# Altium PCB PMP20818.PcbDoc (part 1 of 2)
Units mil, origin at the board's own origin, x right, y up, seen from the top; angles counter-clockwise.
Board outline 3200 x 3200 mil, 4 copper layers (Top Layer, Signal Layer 1, Signal Layer 2, Bottom Layer), stack 61.2 mil thick; 130 components, 48 nets, 295 pads, 106 vias.
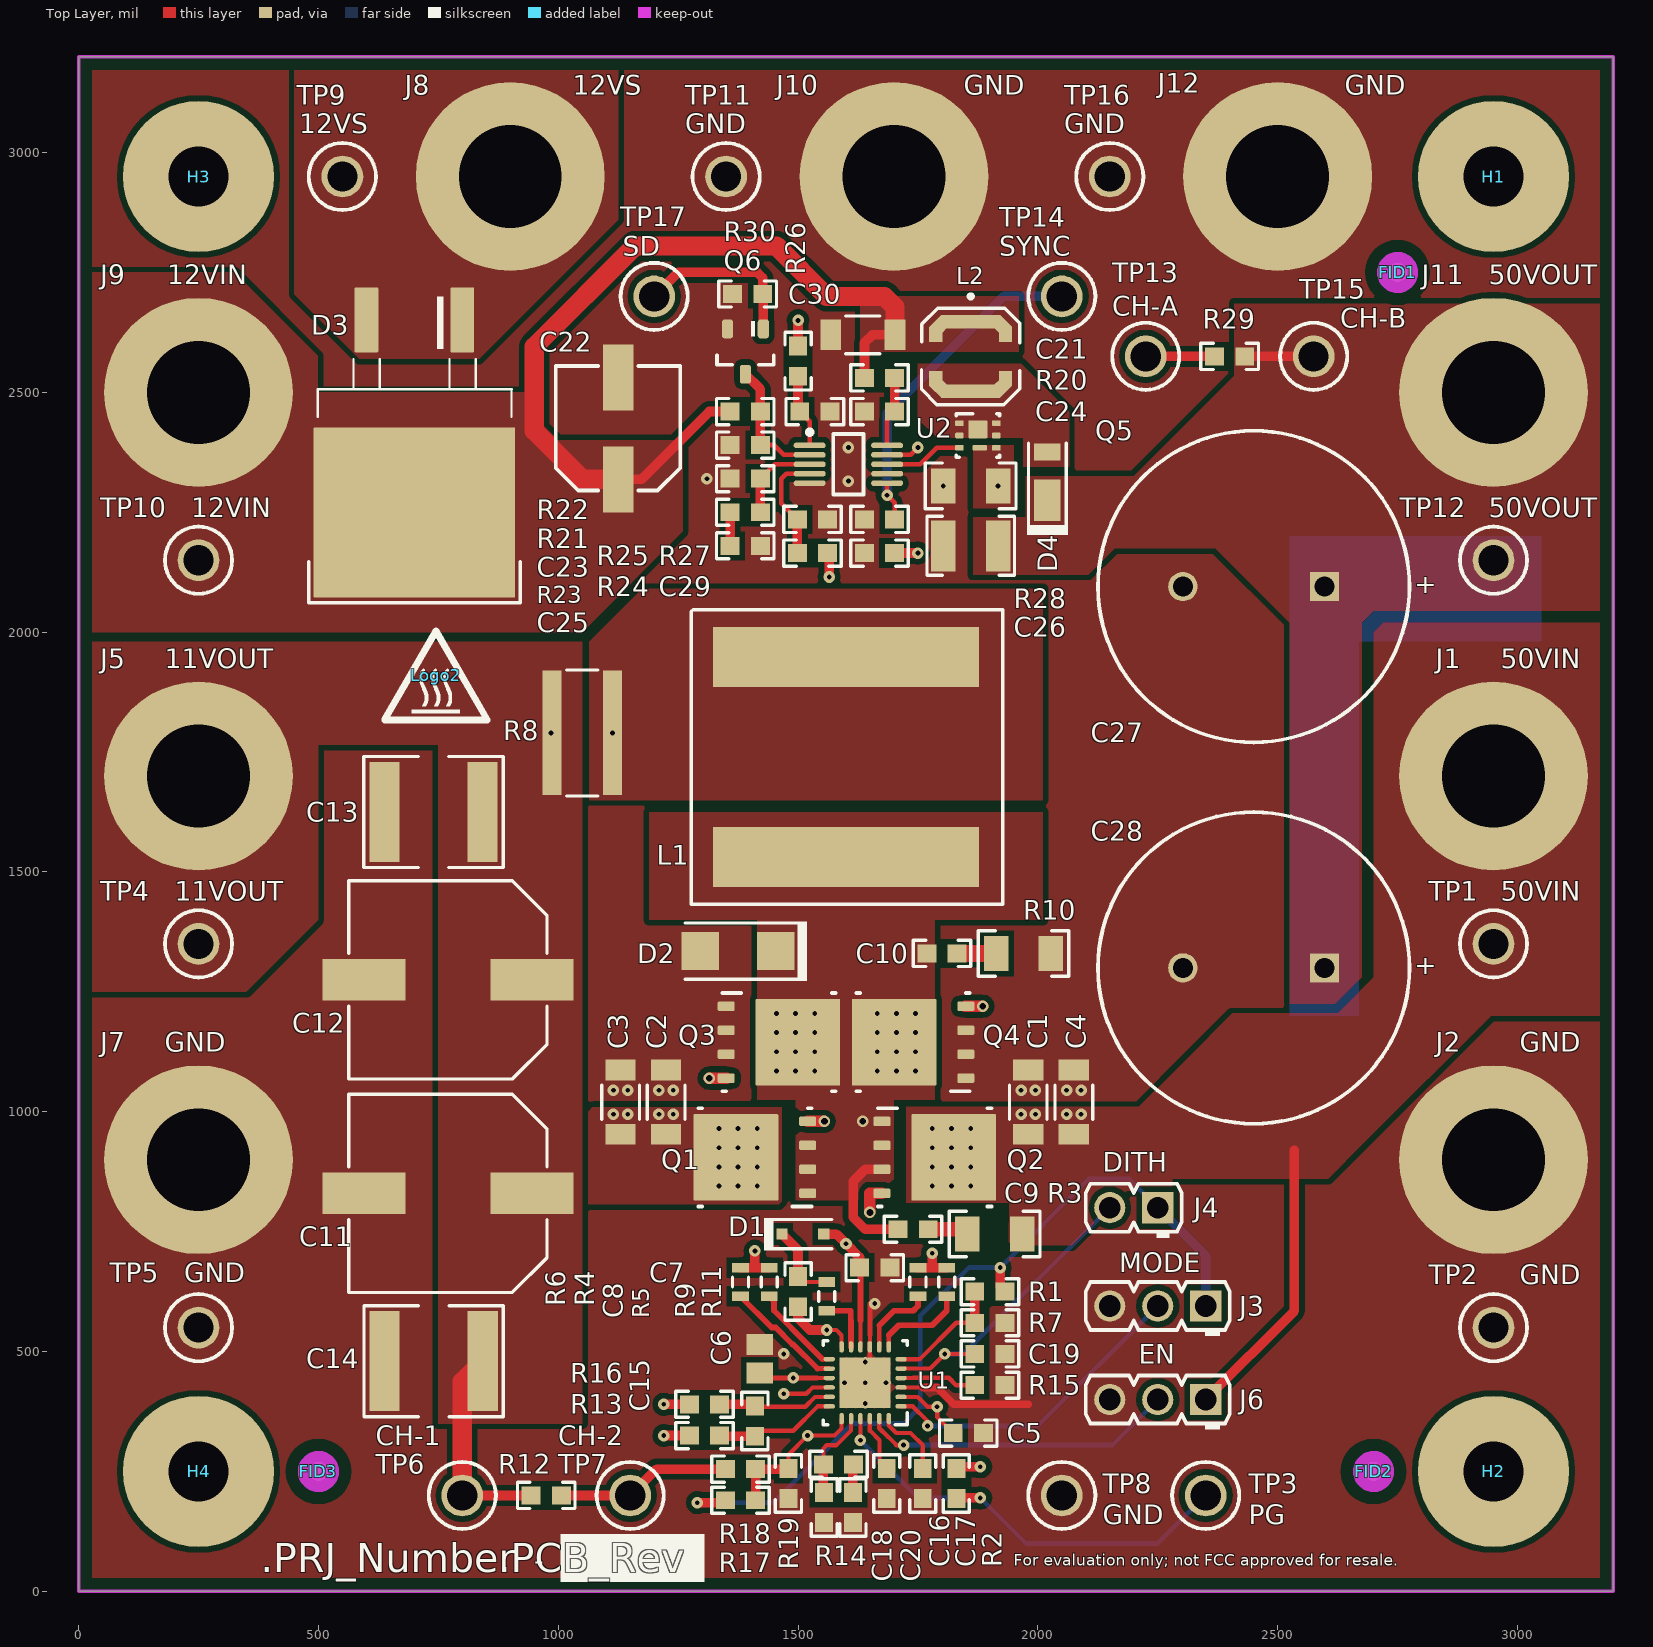
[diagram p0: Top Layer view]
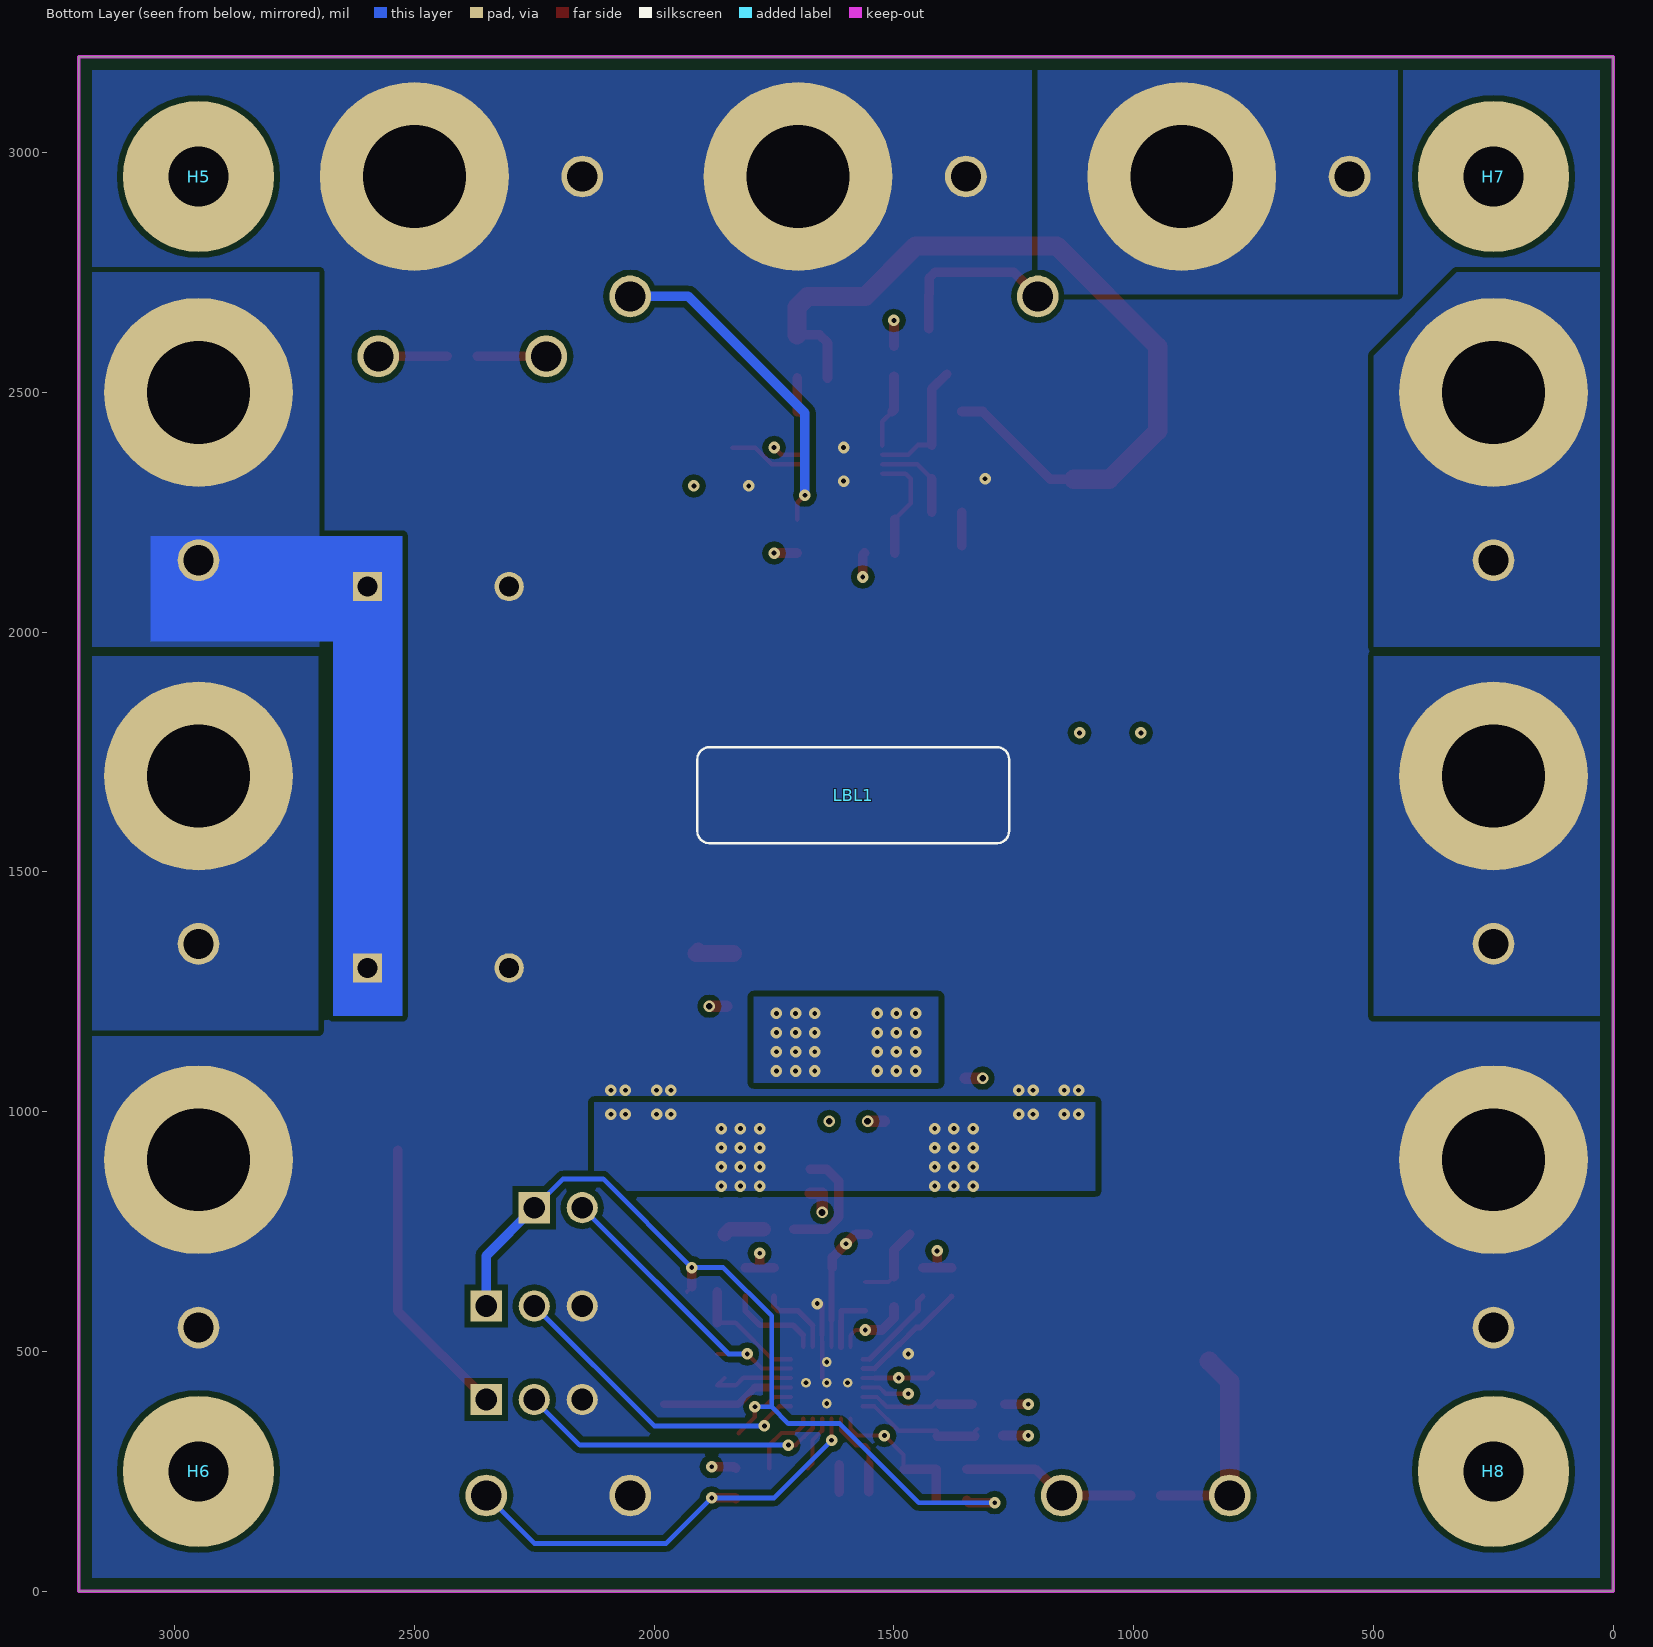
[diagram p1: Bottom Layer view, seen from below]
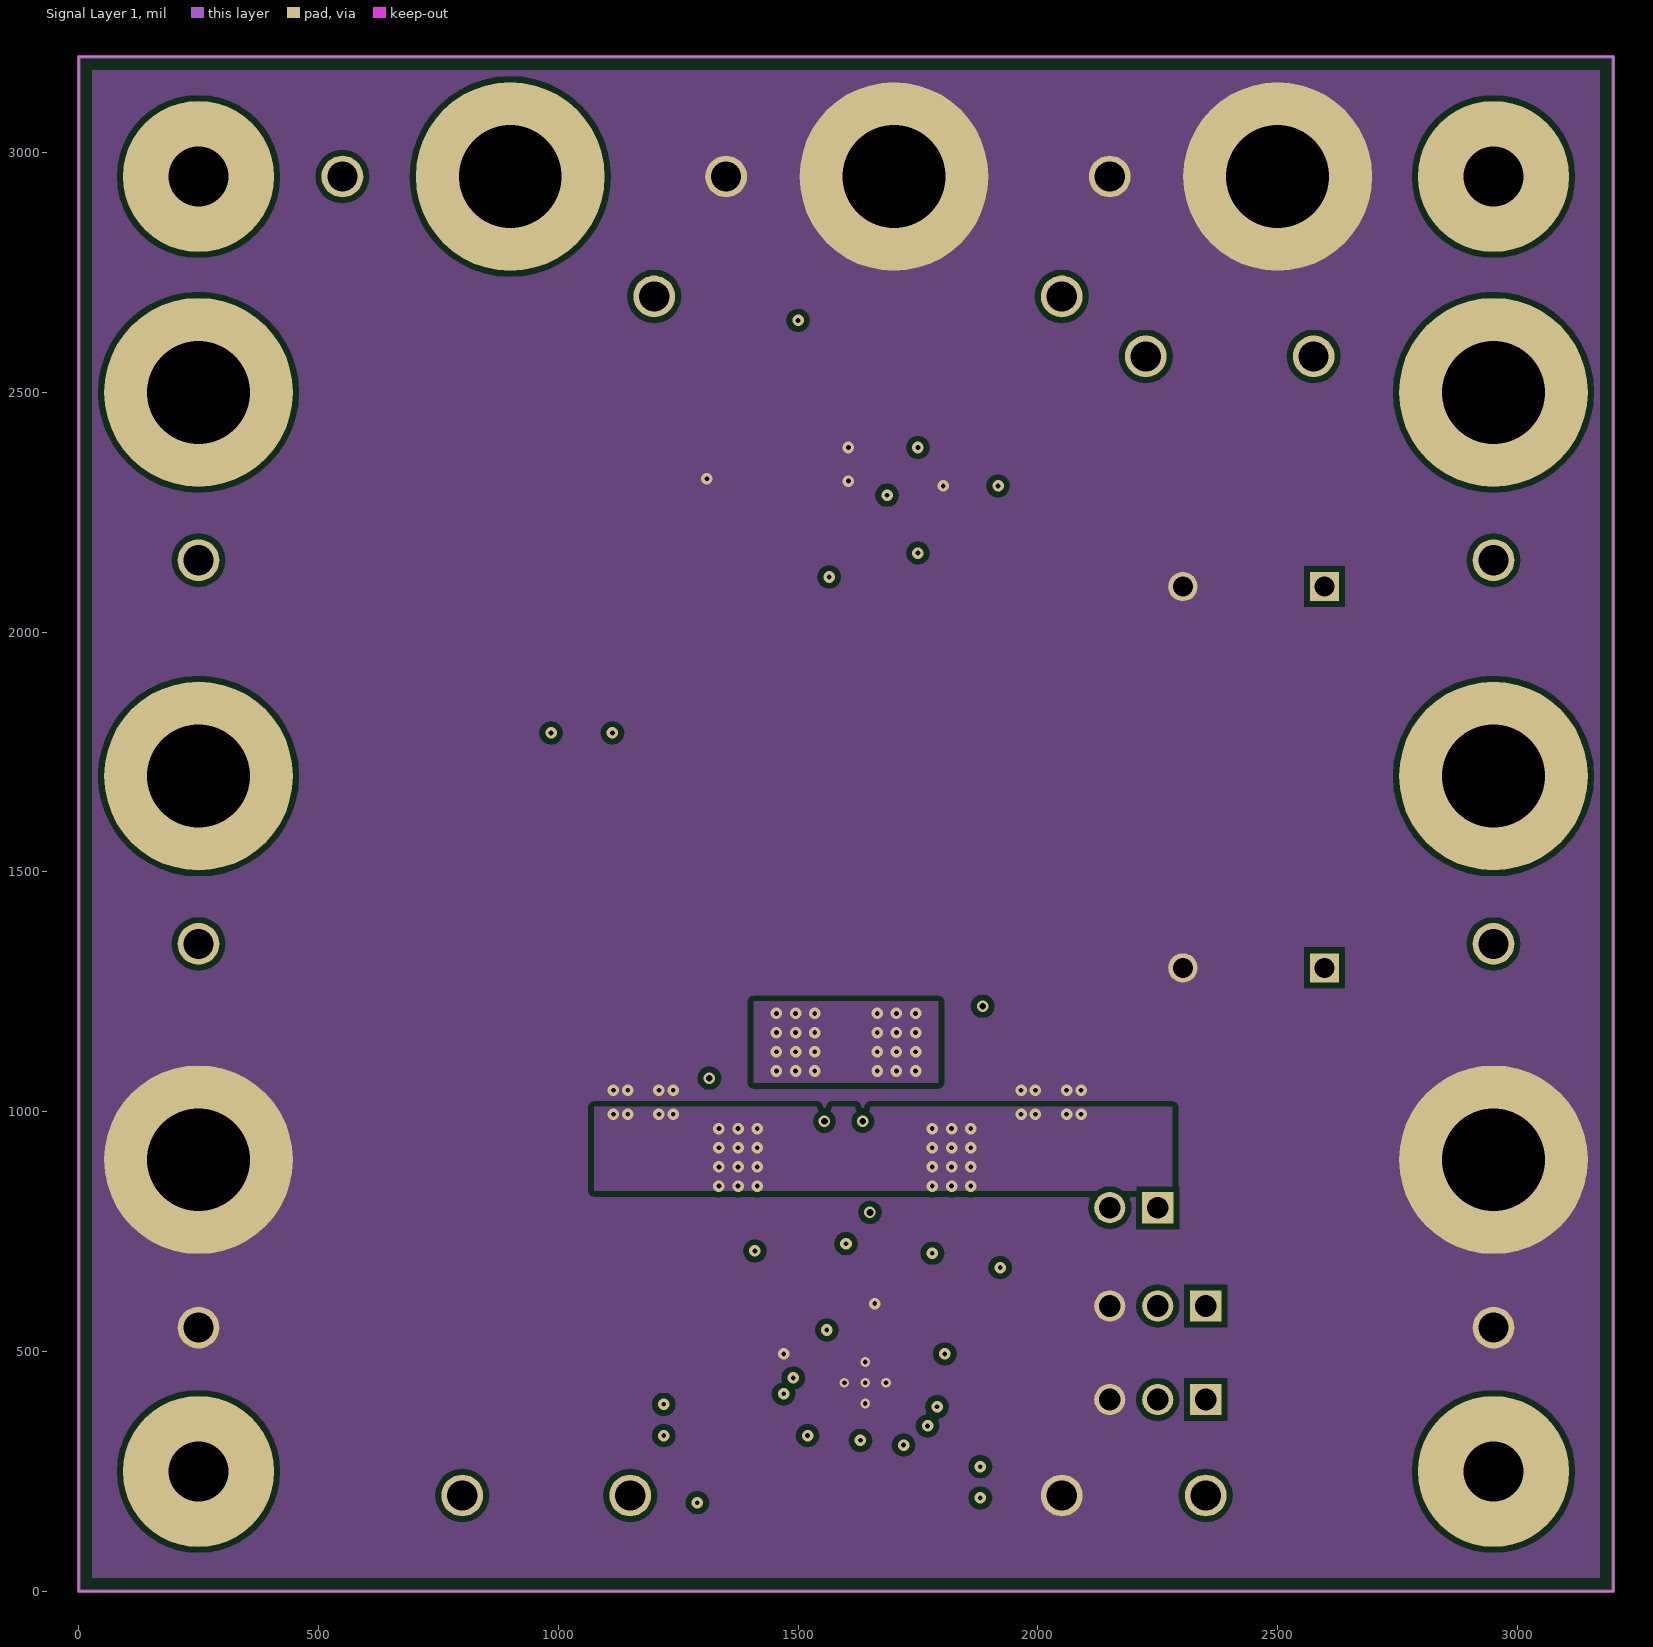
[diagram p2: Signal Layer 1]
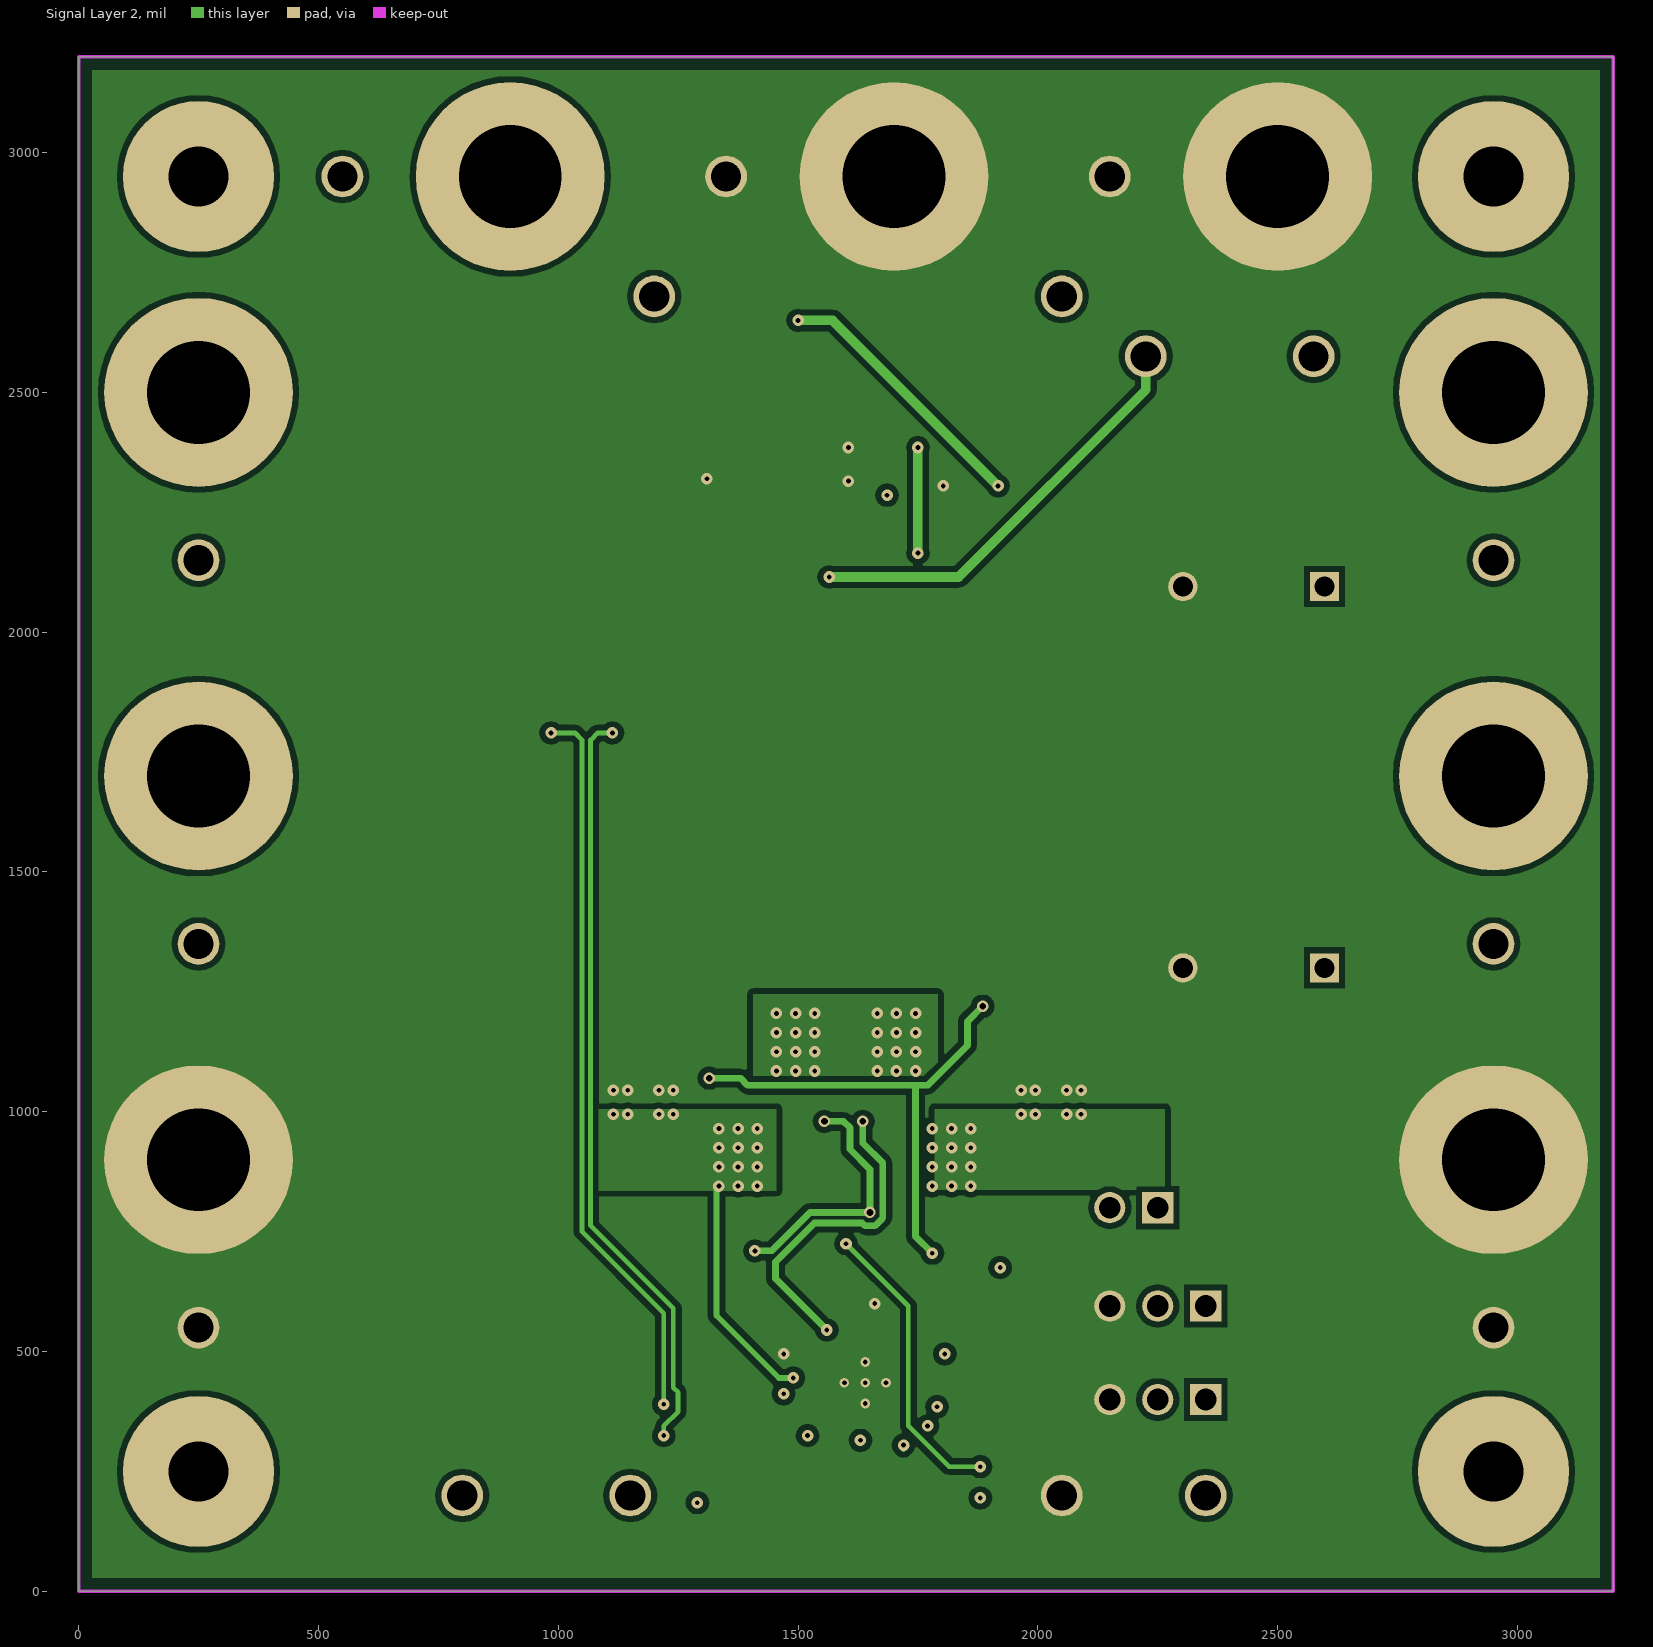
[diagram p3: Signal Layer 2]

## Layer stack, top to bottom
Top Solder: solder mask 0.4, Solder Resist, Dk 3.5
Top Layer: signal copper 2.8
Dielectric1: core 16, FR-4, Dk 4.8
Signal Layer 1: signal copper 2.8
Dielectric 3: prepreg 18, Dk 4.2
Signal Layer 2: signal copper 2.8
Dielectric 2: core 16, FR-4, Dk 4.2
Bottom Layer: signal copper 2.8
Bottom Solder: solder mask 0.4, Solder Resist, Dk 3.5

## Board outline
0,0 3200,0 3200,3200 0,3200

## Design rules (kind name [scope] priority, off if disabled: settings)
AcuteAngle [All] p1: minimum=4.50000000000000E+0001 checktracksonly=FALSE
AssemblyTestPointUsage [All] p1: valid=2
Clearance ClearanceNetTie [HasFootprint('RGE0024H') vs HasFootprint('Net-Tie_10mil')] p1: gap=0
Clearance Clearance_Keepouts [((IsTrack Or IsArc) And Not InPoly) And IsFree and IsKeepOut vs ((IsTrack Or IsArc) And Not InPoly) And IsFree and IsKeepOut] p2: gap=0
Clearance Clearance_BoardEdge_MountingHoles [OnCopper and InComponentClass('Mounting Holes') vs IsKeepOut] p3: gap=40
Clearance Clearance_BoardEdge_Poly [OnCopper and InPoly vs IsKeepOut] p4: gap=25
Clearance Clearance_BoardEdge [OnCopper and Not InComponentClass('Logo') and not InComponentClass('FiducialMark') and not InRegion(1000,500,4000,800) and Not IsKeepout vs IsKeepOut] p5: gap=40
Clearance Clearance_Poly [InPolygon] p6: gap=12
Clearance [All] p7: gap=7.87
ComponentClearance ComponentClearance_L2_L5 [HasFootprint('IHLP2525CZ') vs HasFootprint('IHLP-4040DZ')] p1: gap=0 collisioncheckmode=3 verticalgap=0 showdistances=FALSE
ComponentClearance ComponentClearanceNetTie [HasFootprint('RGE0024H') vs HasFootprint('Net-Tie_10mil')] p2: gap=0 collisioncheckmode=3 verticalgap=0 showdistances=FALSE
ComponentClearance ComponentClearance_MountingHoles_FiducialMarks [InComponentClass('Mounting Holes') vs InComponentClass('FiducialMark')] p3: gap=50 collisioncheckmode=3 verticalgap=10 showdistances=FALSE
ComponentClearance ComponentClearance_Shunt [InComponentClass('Header') vs InComponentClass('Shunt')] p4: gap=0 collisioncheckmode=3 verticalgap=0 showdistances=FALSE
ComponentClearance ComponentClearance_Logo [InComponentClass('Logo')] p5: gap=50 collisioncheckmode=3 verticalgap=10 showdistances=FALSE
ComponentClearance ComponentClearance_ScrewToNut [(HasFootprint('NY PMS 440 0025 PH')) vs (HasFootprint('Keystone_1902C'))] p6: gap=5 collisioncheckmode=3 verticalgap=10 showdistances=FALSE
ComponentClearance ComponentClearance_MountingHoles [InComponentClass('Mounting Holes')] p7: gap=100 collisioncheckmode=3 verticalgap=200 showdistances=FALSE
ComponentClearance ComponentClearance_SmallPassives [HasFootprint('0201*') or HasFootprint('0402*') or HasFootprint('0508') or HasFootprint('0603*') or HasFootprint('0612') or HasFootprint('0805*') or HasFootprint('0815*') or HasFootprint('0830*') or HasFootprint('1206*') or HasFootprint('1210*') or HasFootprint('1808*') or HasFootprint('1812*') or HasFootprint('1825*') or HasFootprint('2010*') or HasFootprint('2220*') or HasFootprint('2225*') or HasFootprint('2512*') or HasFootprint('2728*') or HasFootprint('3518*') vs HasFootprint('0201*') or HasFootprint('0402*') or HasFootprint('0508') or HasFootprint('0603*') or HasFootprint('0612') or HasFootprint('0805*') or HasFootprint('0815*') or HasFootprint('0830*') or HasFootprint('1206*') or HasFootprint('1210*') or HasFootprint('1808*') or HasFootprint('1812*') or HasFootprint('1825*') or HasFootprint('2010*') or HasFootprint('2220*') or HasFootprint('2225*') or HasFootprint('2512*') or HasFootprint('2728*') or HasFootprint('3518*')] p8: gap=20 collisioncheckmode=3 verticalgap=10 showdistances=FALSE
ComponentClearance ComponentClearance_THtoSMT [IsThruComponent vs IsSMTComponent] p9: gap=25 collisioncheckmode=3 verticalgap=30 showdistances=FALSE
ComponentClearance ComponentClearance_THtoTH [IsThruComponent vs IsThruComponent] p10: gap=25 collisioncheckmode=3 verticalgap=30 showdistances=FALSE
ComponentClearance [All] p11: gap=20 collisioncheckmode=3 verticalgap=10 showdistances=FALSE
DiffPairsRouting [All] p1: maxlimit=100 minlimit=10 mostfreqgap=10 toplayer_minwidth=15 toplayer_maxwidth=15 toplayer_prefwidth=15 midlayer1_minwidth=15 midlayer1_maxwidth=15 midlayer1_prefwidth=15 midlayer2_minwidth=15 midlayer2_maxwidth=15 midlayer2_prefwidth=15 bottomlayer_minwidth=15 bottomlayer_maxwidth=15 bottomlayer_prefwidth=15 maxuncoupledlength=1000
FabricationTestPointUsage TestPointUsage [All] p1: valid=2 allowmultiple=FALSE
FabricationTestpoint Testpoint [All] p1: side=3 testpointundercomponent=TRUE minsize=40 maxsize=100 preferedsize=60 minholesize=0 maxholesize=40 preferedholesize=32 testpointgrid=1 allowsidetop=TRUE allowsidebottom=TRUE usegrid=TRUE gridtolerance=0.01
FanoutControl Fanout_LCC [IsLCC] p1: bgadir=Out bgaviamode=Centered fanoutstyle=Auto fanoutdirection=Alternating viagrid=1 // Fanout_LCC (Default Rule)
FanoutControl Fanout_BGA [IsBGA] p2: bgadir=Out bgaviamode=Centered fanoutstyle=Auto fanoutdirection=Alternating viagrid=1 // Fanout_BGA (Default Rule)
FanoutControl Fanout_Default [All] p4: bgadir=Out bgaviamode=Centered fanoutstyle=Auto fanoutdirection=Alternating viagrid=1 // Fanout_Default (Default Rule)
FanoutControl Fanout_Small [(CompPinCount < 5)] p5: bgadir=Out bgaviamode=Centered fanoutstyle=Auto fanoutdirection=OutThenIn viagrid=1 // Fanout_Small (Default Rule)
Height [All] p1: minheight=0 maxheight=1500 prefheight=500
HoleSize [All] p1: absolutevalues=TRUE maxlimit=251 minlimit=8 maxpercent=80.000 minpercent=20.000
MinimumAnnularRing MinimumAnnularRing_ThermalPadVias [IsVia and InAnyComponent] p1: minimumring=5
MinimumAnnularRing [All] p2: minimumring=5
MinimumSolderMaskSliver MinimumSolderMaskSliver_Logo [InComponentClass('Logo') vs InComponentClass('Logo')] p1: minsoldermaskwidth=0.7
MinimumSolderMaskSliver [All] p2: minsoldermaskwidth=3.94
PlaneConnect [All] p1: planeconnectstyle=Direct reliefexpansion=10 reliefentries=4 reliefconductorwidth=10 reliefairgap=10
PolygonConnect [All] p1: connectstyle=Direct reliefconductorwidth=10 reliefentries=4 polygonreliefangle="90 Angle" airgapwidth=10
RoutingVias ThermalPadVias [IsVia and InAnyComponent] p1: holewidth=8 width=18 viastyle="Through Hole" minholewidth=8 minwidth=18 maxholewidth=20 maxwidth=30
RoutingVias [All] p2: holewidth=16 width=34 viastyle="Through Hole" minholewidth=8 minwidth=18 maxholewidth=40 maxwidth=65
SilkToBoardRegionClearance [Not ((IsComment or IsDesignator) And (Hide <> 'False')) and not InRegion(1000,500,4000,800)] p1:
SilkToSilkClearance SilkToSilkClearance_Pb-FreeLogo [(HasFootprint('Pb-Free_Overlay_Medium') OR HasFootprint('Pb-Free_Overlay_Small')) vs (HasFootprint('Pb-Free_Overlay_Medium') OR HasFootprint('Pb-Free_Overlay_Small'))] p1: silktosilkclearance=0
SilkToSilkClearance [All] p2: silktosilkclearance=4
SilkToSolderMaskClearance "Silk to Solder Mask Opening" [All] p1: minsilkscreentomaskgap=3 clearancetoexposedcopper=FALSE
SolderMaskExpansion [All] p1: expansion=1.97
Width [All] p1: maxlimit=250 minlimit=6 preferedwidth=10 checkconnectedcopper=TRUE
14 further rules are at their usual default settings.

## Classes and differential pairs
component class PMP20818_Sh2: C21 C22 C23 C24 C25 C26 C27 C28 C29 C30 D3 D4 J8 J9 J10 J11 J12 L2 Q5 Q6 R20 R21 R22 R23 R24 R25 R26 R27 R28 R29 R30 TP9 TP10 TP11 TP12 TP13 TP14 TP15 TP16 TP17 U2 ZX4 ZX5 ZX6
component class "Mounting Holes": H1 H2 H3 H4
component class PMP20818_Sh3: FID1 FID2 FID3 H1 H2 H3 H4 H5 H6 H7 H8 LBL1 Logo1 Logo2 ZZ1 ZZ2 ZZ3 ZZ4 ZZ5 ZZ6 ZZ7
component class FiducialMark: FID1 FID2 FID3
component class AssemblyNote: ZX1 ZX2 ZX3 ZX4 ZX5 ZX6 ZZ1 ZZ2 ZZ3 ZZ4 ZZ5 ZZ6 ZZ7
component class Label: LBL1
component class Header: J3 J4 J6
component class PMP20818_Sh1: 40 C1 C2 C3 C4 C5 C6 C7 C8 C9 C10 C11 C12 C13 C14 C15 C16 C17 C18 C19 C20 D1 D2 J1 J2 J3 J4 J5 J6 J7 L1 Q1 Q2 Q3 Q4 R1 R2 R3 R4 R5 R6 R7 R8 R9 R10 R11 R12 R13 R14 R15 R16 R17 R18 R19 TP1 TP2 TP3 TP4 TP5 TP6 TP7 TP8 U1 ZX1 ZX2 ZX3

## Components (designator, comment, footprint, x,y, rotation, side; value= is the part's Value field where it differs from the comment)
C1 "UMK316AB7475KL-T" 1206_190 1980,1020 r90 top
C2 "UMK316AB7475KL-T" 1206_190 1225,1020 r90 top
C3 "UMK316AB7475KL-T" 1206_190 1130,1020 r90 top
C4 "UMK316AB7475KL-T" 1206_190 2075,1020 r90 top
C5 "C0603C104K5RACTU" 0603 1855,330 r180 top
C6 "GRM21BR72A474KA73L" 0805L 1420,485 r270 top
C7 "GRM188R61C475KAAJ" 0603 1660,675 r180 top
C8 "CGA3E3X7R1H474K080AB" 0603 1500,625 r270 top
C9 "DNP" 0603 1740,755 r180 top
C10 "DNP" 0603 1800,1330 r0 top
C11 "16SVPE470M" CAPSMT_62_JC0 770,830 r180 top
C12 "16SVPE470M" CAPSMT_62_JC0 770,1275 r180 top
C13 "CGA9N3X7R1C476M230KB" 2220_250 740,1625 r180 top
C14 "CGA9N3X7R1C476M230KB" 2220_250 740.32,480 r180 top
C15 "06035A330JAT2A" 0603 1410,355 r270 top
C16 "GRM188R71E683KA01D" 0603 1685,225 r270 top
C17 "C1608X7R2A103M" 0603 1760,225 r270 top
C18 "GRM1885C1H101JA01D" 0603 1554.45,175 r270 top
C19 "C1608X7R2A103M" 0603 1900,495 r0 top
C20 "GRM188R71E103KA01D" 0603 1614.45,175 r270 top
C21 "GRM31CR71E475KA88L" 1206_180 1635,2620 r180 top
C22 "UUD1E470MCL1GS" SM_RADIAL_6.3AMM 1125,2425 r90 top
C23 "GRM188R71H102KA01D" 0603 1390,2320 r180 top
C24 "06033C104JAT2A" 0603 1670,2460 r180 top
C25 "GRM188R71H103KA01D" 0603 1390,2180 r0 top
C26 "GRM32ER72A225KA35L" 1210 1860,2180 r180 top
C27 "UPW1J102MHD" UPW_1600x3150 2450,2095 r180 top
C28 "UPW1J102MHD" UPW_1600x3150 2450,1300 r180 top
C29 "C1608X7R1C105K" 0603 1670,2165 r180 top
C30 "GRM1885C1H101JA01D" 0603 1535,2460 r0 top
D1 "PMEG6010CEJ,115" SOD-323F 1510,745 r0 top
D2 "SSA210" SMA 1375,1335 r180 top
D3 "MBRB1530CT-T" DDPAK 700,2405 r270 top
D4 "DFLS1100-7" PowerDI123 2020,2325 r90 top
FID1 "Fiducial" Fiducial10-20 2750,2750 r270 top
FID2 "Fiducial" Fiducial10-20 2700,250 r270 top
FID3 "Fiducial" Fiducial10-20 500,250 r270 top
H1 "NY PMS 440 0025 PH" "NY PMS 440 0025 PH" 2950,2950 r270 top locked
H2 "NY PMS 440 0025 PH" "NY PMS 440 0025 PH" 2950,250 r270 top locked
H3 "NY PMS 440 0025 PH" "NY PMS 440 0025 PH" 250,2950 r270 top locked
H4 "NY PMS 440 0025 PH" "NY PMS 440 0025 PH" 250,250 r270 top locked
H5 "1902C" Keystone_1902C 2950,2950 r90 bottom locked
H6 "1902C" Keystone_1902C 2950,250 r90 bottom locked
H7 "1902C" Keystone_1902C 250,2950 r90 bottom locked
H8 "1902C" Keystone_1902C 250,250 r90 bottom locked
J1 "50VIN" Keystone_575-4 2950,1700 r180 top
J2 "GND" Keystone_575-4 2950,900 r0 top
J3 "MODE" WURTH_61300311121 2250,595 r180 top
J4 "DITH" WURTH_61300211121 2200,800 r180 top
J5 "11VOUT" Keystone_575-4 250,1700 r0 top
J6 "EN" WURTH_61300311121 2250,400 r180 top
J7 "GND" Keystone_575-4 250,900 r0 top
J8 "12VS" Keystone_575-4 900,2950 r0 top
J9 "12VIN" Keystone_575-4 250,2500 r0 top
J10 "GND" Keystone_575-4 1700,2950 r0 top
J11 "50VOUT" Keystone_575-4 2950,2500 r0 top
J12 "GND" Keystone_575-4 2500,2950 r0 top
L1 "XAL1510-682MEB" XAL1510 1600,1740 r90 top
L2 "LPS4018-333MLB" LPS4018 1860,2575 r270 top
LBL1 "" Label_650x200 1585,1660 r180 bottom
Logo1 "FCC disclaimer" FCC_disclaimer 3390,2990 r0 top
Logo2 "CAUTION HOT SURFACE" IEC_HotSurface_Small 745,1910 r0 top
Q1 "CSD18534Q5A" DQJ0008A 1410,905 r180 top
Q2 "CSD18534Q5A" DQJ0008A 1785,905 r0 top
Q3 "CSD18534Q5A" DQJ0008A 1460,1145 r0 top
Q4 "CSD18534Q5A" DQJ0008A 1740,1145 r180 top
Q5 "CSD19538Q2" DQK0006C 1875,2410 r0 top
Q6 "2N7002ET1G" SOT-23 1390.31,2585 r270 top
R1 "DNP" 0603 1900,625 r180 top
R2 "CRCW060310K0FKEA" 0603 1830,225 r270 top
R3 "DNP" 1206 1910,745 r0 top
R4 "CRCW06030000Z0EA" 0603S 1440,645 r90 top
R5 "CRCW06030000Z0EA" 0603S 1560,615 r90 top
R6 "CRCW06030000Z0EA" 0603S 1380,645 r270 top
R7 "CRCW06030000Z0EA" 0603 1900,560 r0 top
R8 "KRL6432E-M-R004-F-T1" 2512_WIDE 1050,1790 r180 top
R9 "CRCW06030000Z0EA" 0603S 1750,645 r90 top
R10 "DNP" 1206 1970,1330 r180 top
R11 "CRCW06030000Z0EA" 0603S 1810,645 r270 top
R12 "CRCW060347R0JNEA" 0603 975,200 r180 top
R13 "CRCW060349R9FKEA" 0603 1305,325 r180 top
R14 "CRCW060320K0FKEA" 0603 1584.45,265 r180 top
R15 "DNP" 0603 1899.84,430 r180 top
R16 "CRCW06030000Z0EA" 0603 1305,390 r180 top
R17 "DNP" 0603 1380,190 r0 top
R18 "CRCW060382K5FKEA" 0603 1380,255 r180 top
R19 "CRCW060310K0FKEA" 0603 1480,225 r90 top
R20 "CRCW06034R70JNEA" 0603 1670,2530 r180 top
R21 "CRCW06035K62FKEA" 0603 1390,2390 r180 top
R22 "CRCW060340K2FKEA" 0603 1390,2460 r0 top
R23 "CRCW0603100KFKEA" 0603 1390,2250 r0 top
R24 "CRCW0603487KFKEA" 0603 1530,2165 r180 top
R25 "CRCW060312K7FKEA" 0603 1530,2235 r180 top
R26 "CRCW0603100RFKEA" 0603 1500,2565 r90 top
R27 "CRCW060390K9FKEA" 0603 1670,2235 r180 top
R28 "CSR1206FKR200" 1206 1860,2305 r0 top
R29 "CRCW060347R0JNEA" 0603 2400,2575 r180 top
R30 "CRCW0603100KFKEA" 0603 1395,2705 r0 top
TP1 "50VIN" Keystone5010 2950,1350 r0 top
TP2 "GND" Keystone5011 2950,550 r0 top
TP3 "PG" Keystone5012 2350,200 r0 top
TP4 "11VOUT" Keystone5010 250,1350 r0 top
TP5 "GND" Keystone5011 250,550 r0 top
TP6 "CH-1" Keystone5012 800,200 r0 top
TP7 "CH-2" Keystone5012 1150,200 r0 top
TP8 "GND" Keystone5011 2050,200 r0 top
TP9 "12VS" Keystone5010 550,2950 r0 top
TP10 "12VIN" Keystone5010 250,2150 r0 top
TP11 "GND" Keystone5011 1350,2950 r0 top
TP12 "50VOUT" Keystone5010 2950,2150 r0 top
TP13 "CH-A" Keystone5012 2225,2575 r0 top
TP14 "SYNC" Keystone5012 2050,2700 r0 top
TP15 "CH-B" Keystone5012 2575,2575 r0 top
TP16 "GND" Keystone5011 2150,2950 r0 top
TP17 "SD" Keystone5012 1200,2700 r0 top
U1 "LM5141QRGEQ1" RGE0024H 1640,435 r180 top
U2 "LM3481MM/NOPB" MUB10A_N 1605,2350 r0 top
ZX1 "50VIN = 13 - 50VDC" AssemblyNote 185,4665 r0 top
ZX2 "11VOUT = 11VDC at 13.6A" AssemblyNote 185,4590 r0 top
ZX3 "Fsw = 440kHz" AssemblyNote 185,4510 r0 top
ZX4 "12VIN = 12VDC" AssemblyNote 185,4430 r0 top
ZX5 "50VOUT = 50VDC @ 10mA" AssemblyNote 185,4350 r0 top
ZX6 "Fsw = 250kHz" AssemblyNote 185,4265 r0 top
ZZ1 "This Assembly Note is for PCB labels only" AssemblyNoteLabel 185,4130 r0 top
ZZ2 "These assemblies are ESD sensitive, ESD precautions shall be observed." AssemblyNote 180,4029.11 r0 top
ZZ3 "These assemblies must be clean and free from flux and all contaminants. Use of no clean flux is not acceptable." AssemblyNote 180,3937.97 r0 top
ZZ4 "These assemblies must comply with workmanship standards IPC-A-610 Class 2, unless otherwise specified." AssemblyNote 180,3846.84 r0 top
ZZ5 "Install Shunt Jumper SH-J1 onto J4" AssemblyNote 180,3755.7 r0 top
ZZ6 "Install Shunt Jumper SH-J3 onto J3 pin 2-3." AssemblyNote 185,3665 r0 top
ZZ7 "Install Shunt Jumper SH-J4 onto J6 pins 1-2." AssemblyNote 180,3570 r0 top

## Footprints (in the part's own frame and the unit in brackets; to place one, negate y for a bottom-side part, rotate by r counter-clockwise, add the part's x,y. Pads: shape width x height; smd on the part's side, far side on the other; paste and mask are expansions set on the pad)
0603 [mm] "0603 from SM-752 data"
  rect 1x0.95 smd: 1(-0.8,0) 2(0.8,0)
  silkscreen extent -1.52,-0.69 1.52,0.69, body extent -0.87,-0.47 0.87,0.47, height 1
0603S [mil]
  rect 20x35 smd: 1(-30,0) 2(30,0)
  silkscreen extent -10,-17 10,17, body extent -34,-19 34,19, height 39
0805L [mm] "0805 from SM-752 data"
  rect 1.1x1.4 smd: 1(-0.75,0) 2(0.75,0)
  body extent -1.1,-0.72 1.1,0.72, height 1.45
1206 [mm] "1206 from SM-752 data"
  rect 1.3x1.85 smd: 1(-1.45,0) 2(1.45,0)
  silkscreen extent -2.4,-1.21 2.4,1.21, body extent -1.7,-0.9 1.7,0.9, height 1.35
1206_180 [mm] "1206_180"
  rect 1.1x1.6 smd: 1(-1.7,0) 2(1.7,0)
  silkscreen extent -0.9,-1 0.9,1, body extent -1.75,-0.95 1.75,0.95, height 1.8
1206_190 [mm] "1206_190"
  rect 1.1x1.6 smd: 1(-1.7,0) 2(1.7,0)
  silkscreen extent -0.9,-1 0.9,1, body extent -1.75,-0.95 1.75,0.95, height 1.9
1210 [mm] "1210 from SM-752 data"
  rect 1.3x2.7 smd: 1(-1.45,0) 2(1.45,0)
  silkscreen extent -2.32,-1.57 2.32,1.57, body extent -1.7,-1.35 1.7,1.35, height 1.35
2220_250 [mm] "2220"
  rect 1.6x5.3 smd: 1(-2.6,0) 2(2.6,0)
  silkscreen extent -3.69,-2.94 3.69,2.94, body extent -2.95,-2.62 2.95,2.62, height 2.5
2512_WIDE [mm] "Ohmite recommended land pattern"
  rect 1x6.6 smd: 1(-1.6,0) 2(1.6,0)
  silkscreen extent -0.82,-3.32 0.82,3.35, body extent -1.65,-3.25 1.65,3.25, height 0.7
AssemblyNote [mil] "Assembly Note"
AssemblyNoteLabel [mil] "Assembly Note for PCB Labels"
CAPSMT_62_JC0 [mm] "10 x 12.2mm:  Chemi-Con JC0"
  rect 4.4x2.2 smd: 1(-4.45,0) 2(4.45,0)
  silkscreen extent -5.25,-5.25 5.25,5.25, body extent -5.25,-5.25 5.25,5.25, height 12.7
DDPAK [mil] "D2-PAK, 3-Pads, Body 9.7x10.4mm (max), TO-263AB, using Vishay Silionix recommended pad sizes"
  rrect8% 135x49.49 smd: 1(-246.06,100) 3(-246.06,-100)
  rrect1% 355x420 smd paste-181.1: 4(155.51,0)
  silkscreen extent -295,-220 344,220, body extent -295,-202 324,202, height 180
DQJ0008A [mm] "SMD, 8-Leads, Body 5.75x4.9mm"
  rrect39% 0.91x0.51 smd paste-0.05 mask-0.05: 1(-2.795,1.905) 2(-2.795,0.635) 3(-2.795,-0.635) 4(-2.795,-1.905) 5(2.795,-1.905) 6(2.795,-0.635) 7(2.795,0.635) 8(2.795,1.905)
  rrect8% 1.58x1.25 on Top Paste: 9(-0.38,1.45) 9(-0.38,0) 9(-0.38,-1.45) 9(1.4,1.45) 9(1.4,0) 9(1.4,-1.45)
  rrect3% 3.48x4.47 on Top Solder: 9(0.55,0)
  rrect2% 4.49x4.57 smd paste-2.5 mask-2.5: 9(1.005,0)
  silkscreen extent -3,-2.6 3,2.6, body extent -3.13,-2.45 3.13,2.45, height 1.15
DQK0006C [mm] "WSON"
  rrect12% 0.9x0.86 on Top Paste: 0(0,0.325)
  rrect34% 0.7x0.29 on Top Paste: 0(0.095,-0.65)
  rrect33% 0.45x0.3 smd: 1(-0.975,0.65) 2(-0.975,0) 3(-0.975,-0.65) 4(0.975,-0.65) 5(0.975,0) 6(0.975,0.65)
  rrect33% 0.75x0.3 smd paste-0.15: 7(0.095,-0.65)
  rrect11% 1x0.95 smd paste-0.5: 8(0,0.325)
  silkscreen extent -1.15,-1.15 1.15,1.15, body extent -1,-1 1,1, height 0.82
FCC_disclaimer [mil]
Fiducial10-20 [mm]
  round 1 smd mask+0.5: 1(0,0)
  Top Layer keep-out circle w1.178: c0,0 r0.5
IEC_HotSurface_Small [mil]
  silkscreen extent -107,-93 107,92
Keystone5010 [mil] "Keystone Multipurpose loops"
  round 87 hole 63: 1(0,0)
  silkscreen extent -70,-70 70,70, body extent -63,-63 63,62, height 319
Keystone5011 [mil] "Keystone Multipurpose loops"
  round 87 hole 63: 1(0,0)
  silkscreen extent -70,-70 70,70, body extent -63,-63 63,62, height 319
Keystone5012 [mil] "Keystone Multipurpose loops"
  round 87 hole 63: 1(0,0)
  silkscreen extent -70,-70 70,70, body extent -63,-63 63,62, height 319
Keystone_575-4 [mm] "Banana Jack"
  round 10 hole 5.45: 1(0,0)
  body extent -3.98,-3.95 3.92,3.94, height 2.36
Keystone_1902C [mil] "Hex Standoff, 4-40 threaded, nylon"
  body extent -145,-126 146,126, height 501
Label_650x200 [mil] "Thermal Transfer Label"
  round 1 on Mech14: 0(0,0)
  silkscreen extent -325,-100 325,100, body extent -325,-100 325,100, height 1
LPS4018 [mil]
  rect 28x123 smd: 1(-72.5,0) 2(72.5,0)
  rect 35.5x28 smd rot 45: 1(-64,64) 2(64.5,-63.5)
  rect 35.5x28 smd rot 135: 1(-64,-64) 2(64,64)
  rect 31.5x28 smd: 1(-46,72.5) 1(-46,-72.5) 2(46,72.5) 2(46,-72.5)
  silkscreen extent -129,-102 101,102, body extent -81,-81 81,81, height 71
MUB10A_N [mm] "TSSOP, 10-Leads, Body 3x3mm, Pitch 0.5mm, IPC Medium Density"
  oval 1.7x0.3 smd: 1(-2.05,1) 2(-2.05,0.5) 3(-2.05,0) 4(-2.05,-0.5) 5(-2.05,-1) 6(2.05,-1) 7(2.05,-0.5) 8(2.05,0) 9(2.05,0.5) 10(2.05,1)
  silkscreen extent -2.17,-1.6 0.8,1.82, body extent -1.6,-1.6 1.6,1.6, height 1.09
"NY PMS 440 0025 PH" [mm] "4-40 nylon screw and mounting hole"
  round 8 hole 3.2: 1(0,0)
  body extent -3.3,-3.3 3.3,3.3, height 2.69
PowerDI123 [mm] "Diodes Inc recommended land pattern, document number DS30628 Rev. 6-2"
  rect 2.2x1.4 smd: 1(-1.275,0)
  rect 0.9x1.4 smd: 2(1.275,0)
  silkscreen extent -3.1,-1.09 1.76,1.09, body extent -2.38,-0.97 1.52,0.96, height 1
RGE0024H [mm] "QFN, 24-Leads, Body 4x4mm, Pitch 0.5mm, Thermal Pad 2.7x2.7mm, TI Recommended"
  oval 0.6x0.24 smd: 1(-1.9,1.25) 2(-1.9,0.75) 3(-1.9,0.25) 4(-1.9,-0.25) 5(-1.9,-0.75) 6(-1.9,-1.25) 13(1.9,-1.25) 14(1.9,-0.75) 15(1.9,-0.25) 16(1.9,0.25) 17(1.9,0.75) 18(1.9,1.25)
  oval 0.24x0.6 smd: 7(-1.25,-1.9) 8(-0.75,-1.9) 9(-0.25,-1.9) 10(0.25,-1.9) 11(0.75,-1.9) 12(1.25,-1.9) 19(1.25,1.9) 20(0.75,1.9) 21(0.25,1.9) 22(-0.25,1.9) 23(-0.75,1.9) 24(-1.25,1.9)
  rect 2.7x2.7 smd paste-1.35: 25(0,0)
  silkscreen extent -2.22,-2.22 2.22,2.22, body extent -2.07,-2.07 2.07,2.07, height 1.01
SM_RADIAL_6.3AMM [mm] "Nichicon 6.3x5.8"
  rect 3.5x1.6 smd: 1(-2.7,0) 2(2.7,0)
  silkscreen extent -3.3,-3.29 3.3,3.31, body extent -3.5,-3.3 3.5,3.3, height 6.11
SMA [mm] "Molded Diode, 2-Leads, Body 4.3x2.6mm, IPC Medium Density, based on OnSemi component dimensions and land pattern"
  rect 2x2 smd: 1(-2,0) 2(2,0)
  silkscreen extent -3.66,-1.57 2.79,1.57, body extent -2.6,-1.3 2.6,1.3, height 2.42
SOD-323F [mm] "NXP recommended land pattern"
  rect 0.6x0.6 smd paste-0.05: 1(-1.1,0) 2(1.1,0)
  silkscreen extent -2.06,-0.86 1.53,0.86, body extent -1.35,-0.67 1.35,0.68, height 0.79
SOT-23 [mm] "SOT23, 3-Leads, Body 2.9x1.3mm, Pitch 0.95mm, Lead Span 2.5mm, IPC Medium Density"
  rrect50% 1x0.6 smd: 1(-1.2,0.95) 2(-1.2,-0.95) 3(1.2,0)
  silkscreen extent -1.63,-1.5 0.7,1.5, body extent -1.16,-1.45 1.21,1.45, height 1
UPW_1600x3150 [mm] "TH, 2-Leads, Dia 16mm, Pin Spacing 7.5mm"
  rect 1.55x1.55 hole 1.05: 1(-3.75,0)
  round 1.55 hole 1.05: 2(3.75,0)
  silkscreen extent -8.25,-8.25 8.25,8.25, body extent -8.19,-8.24 8.23,8.24, height 33.51
WURTH_61300211121 [mm] "Header, 2.54mm, 2x1, TH"
  rect 1.65x1.65 hole 1.15: 1(-1.27,0)
  round 1.65 hole 1.15: 2(1.27,0)
  silkscreen extent -2.54,-1.27 2.54,1.6, body extent -2.54,-1.27 2.54,1.27, height 8.54
WURTH_61300311121 [mm] "Header, 2.54mm, 3x1, TH"
  rect 1.65x1.65 hole 1.15: 1(-2.54,0)
  round 1.65 hole 1.15: 2(0,0) 3(2.54,0)
  silkscreen extent -3.81,-1.27 3.81,1.6, body extent -3.81,-1.27 3.81,1.27, height 8.54
XAL1510 [mm] "COILCRAFT"
  rect 3.18x14.1 smd: 1(-5.3,0) 2(5.3,0)
  silkscreen extent -7.8,-8.3 7.8,8.2, body extent -7.7,-8.2 7.7,8.2, height 11

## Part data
C1 C2 C3 C4: "CAP, CERM, 4.7 µF, 50 V, +/- 10%, X7R, 1206_190"
C5: "CAP, CERM, 0.1 µF, 50 V, +/- 10%, X7R, 0603"
C6: "CAP, CERM, 0.47 µF, 100 V, +/- 10%, X7R, 0805"
C7: "CAP, CERM, 4.7 µF, 16 V, +/- 10%, X5R, 0603"
C8: "CAP, CERM, 0.47 µF, 50 V, +/- 10%, X7R, AEC-Q200 Grade 1, 0603"
C9 C10: library part GRM1885C2A102JA01D, "CAP, CERM, 1000 pF, 100 V, +/- 5%, C0G/NP0, 0603"
C11 C12: "CAP, Aluminum Polymer, 470 µF, 16 V, +/- 20%, 0.01 ohm, JC0 SMD"
C13 C14: "CAP, CERM, 47 µF, 16 V, +/- 20%, X7R, AEC-Q200 Grade 1,"
C15: "CAP, CERM, 33 pF, 50 V, +/- 5%, C0G/NP0, 0603"
C16: "CAP, CERM, 0.068 µF, 25 V, +/- 10%, X7R, 0603"
C17 C19: "CAP, CERM, 0.01 µF, 100 V, +/- 20%, X7R, 0603"
C18 C30: "CAP, CERM, 100 pF, 50 V, +/- 5%, C0G/NP0, 0603"
C20: "CAP, CERM, 0.01 µF, 25 V, +/- 10%, X7R, 0603"
C21: "CAP, CERM, 4.7 µF, 25 V, +/- 10%, X7R, 1206"
C22: "CAP, AL, 47 µF, 25 V, +/- 20%, 0.44 ohm, SMD"
C23: "CAP, CERM, 1000 pF, 50 V, +/- 10%, X7R, 0603"
C24: "CAP, CERM, 0.1 µF, 25 V, +/- 5%, X7R, 0603"
C25: "CAP, CERM, 0.01 µF, 50 V, +/- 10%, X7R, 0603"
C26: "CAP, CERM, 2.2 µF, 100 V, +/- 10%, X7R, 1210"
C27 C28: "CAP, AL, 1000 µF, 63 V, +/- 20%, 0.043 ohm, TH"
C29: "CAP, CERM, 1 µF, 16 V, +/- 10%, X7R, 0603"
D1: "Diode, Schottky, 60 V, 1 A, SOD-323F"
D2: "Diode, Schottky, 100 V, 2 A, AEC-Q101, SMA"
D3: "Diode, Schottky, 30 V, 15 A, DDPAK"
D4: "Diode, Schottky, 100 V, 1 A, PowerDI123"
FID1 FID2 FID3: "Fiducial mark.  There is nothing to buy or mount."
H1 H2 H3 H4: "Machine Screw, Round, #4-40 x 1/4, Nylon, Philips panhead"
H5 H6 H7 H8: "Standoff, Hex, 0.5\"L #4-40 Nylon"
J1 J2 J5 J7 J8 J9 J10 J11 J12: library part 575-4, "Standard Banana Jack, Uninsulated, 5.5mm"
J3 J6: library part 61300311121, "Header, 2.54 mm, 3x1, Gold, TH"
J4: library part 61300211121, "Header, 2.54 mm, 2x1, Gold, TH"
L1: "Inductor, Shielded, Composite, 6.8 µH, 26 A, 0.00417 ohm, SMD"
L2: "Inductor, Shielded Drum Core, Ferrite, 33 µH, 0.68 A, 0.42 ohm, SMD"
LBL1: library part THT-14-423-10, "Thermal Transfer Printable Labels, 0.650\" W x 0.200\" H - 10,000 per roll"
Logo1: library part FCC_disclaimer, "FCC_disclaimer"
Logo2: library part IEC_HotSurface, "IEC 61010-1 Hot Surface Warning"
Q1 Q2 Q3 Q4: "MOSFET, N-CH, 60 V, 50 A, DQJ0008A (VSONP-8)"
Q5: "MOSFET, N-CH, 100 V, 4.5 A, DQK0006C (WSON-6)"
Q6: "MOSFET, N-CH, 60 V, 0.26 A, SOT-23"
R1 R17: library part CRCW06030000Z0EA, "RES, 0, 5%, 0.1 W, 0603"
R2 R19: "RES, 10.0 k, 1%, 0.1 W, 0603"
R3 R10: library part CRM1206-JW-1R0ELF, "RES, 1.0, 5%, 0.5 W, 1206"
R4 R5 R6 R7 R9 R11 R16: "RES, 0, 5%, 0.1 W, 0603"
R8: library part KRL6432E-M-R007-F-T1, "RES, 0.004, 1%, 3 W, 2512 WIDE"
R12 R29: "RES, 47, 5%, 0.1 W, 0603"
R13: "RES, 49.9, 1%, 0.1 W, 0603"
R14: "RES, 20.0 k, 1%, 0.1 W, 0603"
R15: library part CRCW060349K9FKEA, "RES, 49.9 k, 1%, 0.1 W, 0603"
R18: "RES, 82.5 k, 1%, 0.1 W, 0603"
R20: "RES, 4.7, 5%, 0.1 W, 0603"
R21: "RES, 5.62 k, 1%, 0.1 W, 0603"
R22: "RES, 40.2 k, 1%, 0.1 W, 0603"
R23 R30: "RES, 100 k, 1%, 0.1 W, 0603"
R24: "RES, 487 k, 1%, 0.1 W, 0603"
R25: "RES, 12.7 k, 1%, 0.1 W, 0603"
R26: "RES, 100, 1%, 0.1 W, 0603"
R27: "RES, 90.9 k, 1%, 0.1 W, 0603"
R28: "RES, 0.2, 1%, 0.5 W, 1206"
TP1 TP4 TP9 TP10 TP12: library part 5010, "Test Point, Multipurpose, Red, TH"
TP2 TP5 TP8 TP11 TP16: library part 5011, "Test Point, Multipurpose, Black, TH"
TP3 TP6 TP7 TP13 TP14 TP15 TP17: library part 5012, "Test Point, Multipurpose, White, TH"
U1: "IC, PWM, Buck Controller, w/ Dither"
U2: "High Efficiency Low-Side N-Channel Controller for Switching Regulators, 10-pin MSOP, Pb-Free"
ZX1 ZX2 ZX3 ZX4 ZX5 ZX6: library part AssemblyNote, "This Assembly Note will show in the PcbDoc and associated outputs"
ZZ1: library part AssemblyNoteLabel
ZZ2 ZZ3 ZZ4 ZZ5 ZZ6 ZZ7: library part AssemblyNote

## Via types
v1: diameter 24, hole 10, Top Layer to Bottom Layer, 69 vias
v2: diameter 24, hole 10, Top Layer to Bottom Layer, tented both sides, 27 vias
v3: diameter 24, hole 14, Top Layer to Bottom Layer, 5 vias
v4: diameter 20, hole 10, Top Layer to Bottom Layer, 5 vias

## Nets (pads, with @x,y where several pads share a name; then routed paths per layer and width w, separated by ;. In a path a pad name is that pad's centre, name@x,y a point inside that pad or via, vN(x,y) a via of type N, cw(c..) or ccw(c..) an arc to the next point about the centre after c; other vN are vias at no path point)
11VOUT: C11.1 C12.1 C13.1 C14.1 J5.1 R8.2 R12.2 R16.2 TP4.1 TP6.1 | length 2016.3
  Top Layer w20: TP6.1@800,200 R12.2@943.5,200 ; v2(1220,390) R16.2@1268.5,390
  Top Layer w40: TP6.1@800,200 800,437.32 C14.1@842.68,480
  Signal Layer 2 w10: v1(985.06,1790) 1035,1790 1049.5,1775.5 1049.5,750.5 1220,580 v2(1220,390)
12VIN: C21.1 C22.1 D3.4 J9.1 L2.1 R20.2 R22.1 TP10.1 | length 1777.3
  Top Layer w20: C22.1@1125,2318.7 1173.7,2318.7 1315,2460 R22.1@1358.5,2460 ; R20.2@1638.5,2530 1638.5,2603.5 1655,2620 C21.1@1701.93,2620
  Top Layer w40: C22.1@1125,2318.7 1051.3,2318.7 950,2420 950,2595 1160,2805 1455,2805 1560,2700 1680,2700 1701.93,2678.07 C21.1@1701.93,2620
12VS: D3.1 D3.3 J8.1 TP9.1
50VIN: C1.1 C2.1 C3.1 C4.1 C6.2 J1.1 J6.1 Q1.5 Q1.6 Q1.7 Q1.8 Q1.9@1370.43,905 Q2.5 Q2.6 Q2.7 Q2.8 Q2.9@1824.57,905 R3.2 TP1.1 U1.15 | length 1246.4
  Top Layer w9: 1530.16,444.84 U1.15@1565.2,444.84
  Top Layer w11: C6.2@1420,455.47 1430.47,445 v2(1490,445) 1530.13,444.87 ; 1530,445 1530.16,444.84 ; 1539.59,444.84 1530.13,444.87
  Top Layer w20: J6.1@2350,400 2535,585 2535,920
  Signal Layer 2 w12: v1@1330,845 1330,575.24 1460.24,445 v2(1490,445)
  Bottom Layer w10: v2(1490,445) v2@1494.87,440.13
  other v1: 1335,845 1375,845 1415,845 1780,845 1820,845 1860,845 1335,885 1375,885 1415,885 1780,885 1820,885 1860,885 1335,925 1375,925 1415,925 1780,925 1820,925 1860,925 1335,965 1375,965 1415,965 1780,965 1820,965 1860,965 1115,995 1145,995 1210,995 1240,995 1965,995 1995,995 2060,995 2090,995
50VOUT: C26.1 C27.1 C28.1 D4.1 J11.1 R29.1 TP12.1 TP15.1 | length 143.5
  Top Layer w20: R29.1@2431.5,2575 TP15.1@2575,2575
BODE: R12.1 R18.2 TP7.1 | length 364.8
  Top Layer w20: R12.1@1006.5,200 TP7.1@1150,200 1205,255 R18.2@1348.5,255
COMP: C18.1 R14.2 U1.20 | length 187.7
  Top Layer w9: R14.2@1552.95,265 1552.95,297.95 1560,305 1580,305 1610.47,335.47 U1.20@1610.47,360.2
  Top Layer w20: C18.1@1552.95,207.99 R14.2@1552.95,265
CS: C15.2 R13.1 U1.18 | length 262.4
  Top Layer w9: R13.1@1326.5,338.5 R13.1@1331.5,333.5 ; C15.2@1410,333.5 1411.5,335 1490,335 1540.79,385.79 U1.18@1565.2,385.79
  Top Layer w20: R13.1@1331.5,323.5 C15.2@1410,323.5
DEMB: J3.2 U1.1 | length 661.5
  Top Layer w9: U1.1@1714.8,385.79 1739.21,385.79 1770,355 v2(1770,345)
  Bottom Layer w10: v2(1770,345) 2000,345 J3.2@2250,595
DITH: C19.1 J4.2 U1.5 | length 636.7
  Top Layer w9: U1.5@1714.8,464.53 1775.51,464.53 v2(1805.99,495) C19.1@1868.5,495
  Bottom Layer w10: v2(1805.99,495) 1845,495 J4.2@2150,800
DR: Q5.3 U2.8 | length 165.2
  Top Layer w10: U2.8@1685.71,2350 1755,2350 1789.41,2384.41 Q5.3@1836.61,2384.41
EN: J6.2 U1.23 | length 661.5
  Top Layer w9: U1.23@1669.53,360.2 1669.53,340.07 1686.87,322.72 1687.28,322.72 1705,305 v2(1720,305)
  Signal Layer 2 w9: v2@1715,300 v2@1720,295
  Bottom Layer w10: v2(1720,305) 2155,305 J6.2@2250,400
GND: C1.2 C2.2 C3.2 C4.2 C5.1 C6.1 C7.1 C11.2 C12.2 C13.2 C14.2 C16.2 C17.2 C18.2 C19.2 C20.2 C21.2 C22.2 C23.2 C24.2 C25.2 C26.2 C27.2 C28.2 C29.2 C30.2 D2.2 J2.1 J3.3 J6.3 J7.1 J10.1 J12.1 Q3.1 Q3.2 Q3.3 Q4.1 Q4.2 Q4.3 Q6.2 R7.2 R10.1 R15.1 R19.1 R21.2 R25.1 R27.2 R28.1 R30.1 TP2.1 TP5.1 TP8.1 TP11.1 TP16.1 U1.3 U1.9 U1.25 U2.5 U2.7 | length 435.6
  Top Layer w9: U1.25@1649.84,444.84 U1.9@1649.84,509.8 1650,535 ; U1.3@1714.8,425.16 1759.84,425.16
  Top Layer w11: 1650,535 1650,555.87 ; v2@1650,600 1650,555.87 ; 1650.15,556.03 1650,555.87
  Top Layer w16: 1759.84,425.16 1790,425.16 1790,424.42 1824.42,390 1980,390
  other v1: 1115,1045 1145,1045 1210,1045 1240,1045 1965,1045 1995,1045 2060,1045 2090,1045
  other v2: 1470,495 1660,600 1802.91,2305 1605,2315 1310,2320 1605,2385
  other v4: 1640,391.69 1596.69,435 1640,435 1683.31,435 1640,478.31
HB: R5.1 U1.11 | length 125.5
  Top Layer w12: R5.1@1560,585 1610,585 1610,565 1610.28,564.72 1610.28,509.8 U1.11@1610.47,509.8
HG: Q1.4 Q2.4 R4.2 R6.1 | length 720.8
  Top Layer w20: R6.1@1380,675 1410,675 ; v1(1410,710) 1410,675 ; R4.2@1440,675 1410,675
  Top Layer w24: Q1.4@1520.04,980 v3(1555,980) ; v3(1650,790) 1650,830 Q2.4@1674.96,830
  Signal Layer 2 w14: v1(1410,710) 1445,710 1525,790 v3(1650,790) 1650,880 1608.13,921.87 1608.13,966.87 1595,980 v3(1555,980)
HO: R4.1 U1.13 | length 191.1
  Top Layer w10: 1550.79,484.21 U1.13@1565.2,484.21
  Top Layer w12: R4.1@1440,615 1450,605 1450,585.43 1520.43,515 1520.43,514.57 1550.79,484.21
HOL: R6.2 U1.14 | length 247.5
  Top Layer w10: 1540.47,464.53 U1.14@1565.2,464.53
  Top Layer w12: R6.2@1380,615 1380.06,615 1445,550.06 1453.31,550.06 1488.36,515 1490,515 1540.47,464.53
ISEN: C30.1 R26.1 U2.1 | length 154.2
  Top Layer w10: C30.1@1503.5,2460 1524.29,2439.21 U2.1@1524.29,2389.37
  Top Layer w20: R26.1@1500,2533.5 1500,2463.5 C30.1@1503.5,2460
LG: Q3.4 Q4.4 R9.2 R11.1 | length 1202
  Top Layer w20: R9.2@1750,675 1780,675 ; v1(1780,705) 1780,675 ; R11.1@1810,675 1780,675
  Top Layer w24: v3(1315,1070) Q3.4@1349.96,1070 Q3.4@1351.83,1070 ; Q4.4@1848.17,1220 v3(1885,1220)
  Signal Layer 2 w14: v3(1315,1070) 1380,1070 1395,1055 1745,1055 ; v1(1780,705) 1745,740 1745,1055 ; v3(1885,1220) 1853.39,1188.39 1853.39,1138.39 1770,1055 1745,1055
